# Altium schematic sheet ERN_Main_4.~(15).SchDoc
size A; SheetNumber: 4; SheetTotal: 4; SPICEModelCacheELVNKBHK: <root> / <DocumentId>ELVNKBHK</DocumentId> / <CacheFrame Number="0"> / <Model Name="led2" Kind="MDL"> / <Text>*Typ RED,GREEN,YELLOW,AMBER GaAs LED: Vf=2.1V Vr=4V If=40mA trr=3uS / *LED Pinout: 1=A, 2=K / .MODEL LED2 D (IS=93.1P RS=42M N=4.61 BV=4 IBV=10U / + CJO=2.97P VJ=.75 M=.333 TT=4.32U)</Text> / </Model> / </CacheFrame> / </root>
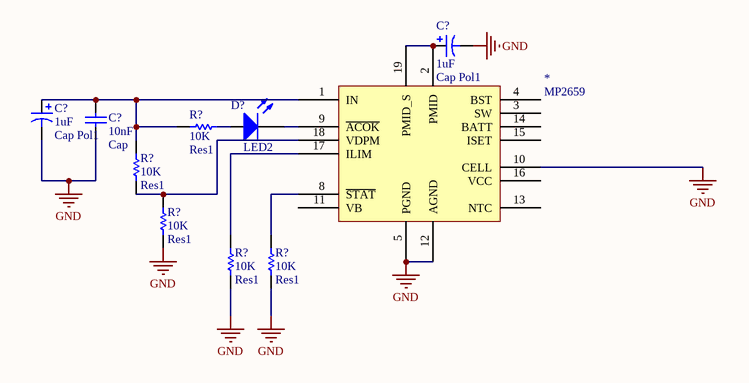
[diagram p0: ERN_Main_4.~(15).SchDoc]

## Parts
(Parts that share a designator on the sheet are numbered #1, #2 ... from top to bottom, then left to right.)
*  MP2659
C?#1  Cap Pol1  value 1uF  [RB7.6-15]
C?#2  Cap Pol1  value 1uF  [RB7.6-15]
C?#3  Cap  value 10nF  [RAD-0.3]
D?  LED2  [3.2X1.6X1.1]
R?#1  Res1  value 10K  [AXIAL-0.3]
R?#2  Res1  value 10K  [AXIAL-0.3]
R?#3  Res1  value 10K  [AXIAL-0.3]
R?#4  Res1  value 10K  [AXIAL-0.3]
R?#5  Res1  value 10K  [AXIAL-0.3]

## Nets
GND: *.5(PGND) *.10(CELL) *.12(AGND) C?#1.2 C?#2.2 C?#3.1 R?#3.2 R?#4.2 R?#5.2
Net*_1: *.1(IN) C?#2.1 C?#3.2 R?#1.2 R?#2.1
Net*_2: *.2(PMID) *.19(PMID_S) C?#1.1
Net*_8: *.8(~{STAT}) R?#5.1
Net*_9: *.9(~{ACOK}) D?.2(K)
Net*_17: *.17(ILIM) R?#4.1
Net*_18: *.18(VDPM) R?#2.2 R?#3.1
NetD?_1: D?.1(A) R?#1.1

Not connected (* = marked no-connect by the designer): * 3(SW) 4(BST) 11(VB) 13(NTC) 14(BATT) 15(ISET) 16(VCC)

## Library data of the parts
* = MP2659: 3S-6S Standalone Switching Charger
C?#1 C?#2 = Cap Pol1: Polarized Capacitor (Radial)
C?#3 = Cap: Capacitor
D? = LED2: Typical RED, GREEN, YELLOW, AMBER GaAs LED
R?#1-R?#5 = Res1: Resistor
